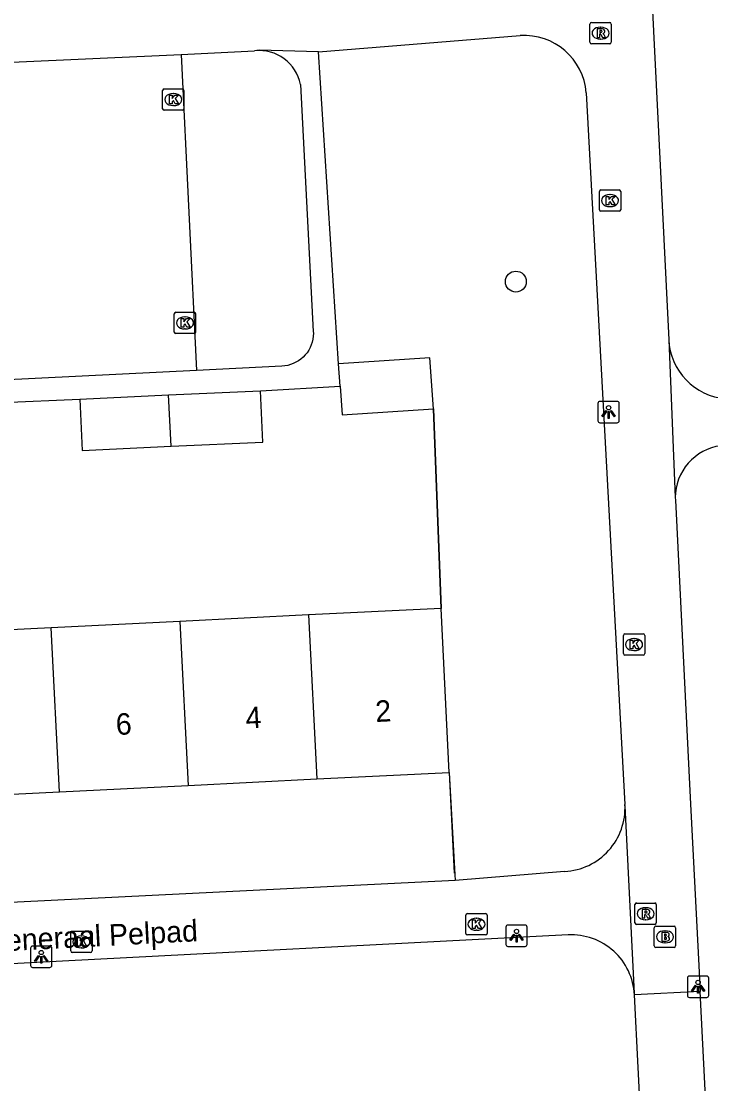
# Model space of a CAD drawing. Extents: x 161084 to 161928, y 385355 to 386522.
# Drawn here: x 161332.38 to 161364.67, y 385622.14 to 385671.84 of the extents above; entities that cross this region are included whole.
import ezdxf

# ---------------------------------------------------------------- set-up
doc = ezdxf.new("R2010")
doc.units = 0
for name, color, linetype in [('IMGEO_Boom', 7, 'Continuous'), ('IMGEO_Brandkraan', 7, 'Continuous'), ('IMGEO_Groenvoorziening', 7, 'Continuous'), ('IMGEO_Hek', 7, 'Continuous'), ('IMGEO_Kolk', 7, 'Continuous'), ('IMGEO_Lichtpunt', 7, 'Continuous'), ('IMGEO_Openbare_ruimte_label', 7, 'Continuous'), ('IMGEO_Pand', 7, 'Continuous'), ('IMGEO_Pand_nummerreeks', 7, 'Continuous'), ('IMGEO_Rijbaan_lokaal_open', 7, 'Continuous'), ('IMGEO_Rioolput', 7, 'Continuous'), ('IMGEO_Voetpad_open', 7, 'Continuous')]:
    doc.layers.add(name, color=color, linetype=linetype)

msp = doc.modelspace()

# ---------------------------------------------------------------- linework, layer by layer
at = {"layer": 'IMGEO_Boom'}
msp.add_circle((161355.54, 385659.662), 0.489, dxfattribs=at)
at = {"layer": 'IMGEO_Brandkraan'}
for p, q in [((161362.02, 385628.59), (161362.02, 385629.442)), ((161362.095, 385629.516), (161362.947, 385629.516)), ((161362.508, 385629.296), (161362.533, 385629.296)), ((161363.021, 385629.442), (161363.021, 385628.59)), ((161362.531, 385628.736), (161362.506, 385628.736)), ((161362.947, 385628.516), (161362.095, 385628.516))]:
    msp.add_line(p, q, dxfattribs=at)
for points in [[(161362.02, 385628.59), (161362.02, 385629.442)], [(161362.095, 385629.516), (161362.947, 385629.516)], [(161362.368, 385629.216), (161362.368, 385628.816), (161362.581, 385628.816)], [(161362.599, 385629.216), (161362.368, 385629.216)], [(161362.547, 385629.135), (161362.493, 385629.135), (161362.493, 385629.059)], [(161363.021, 385629.442), (161363.021, 385628.59)], [(161362.493, 385629.059), (161362.546, 385629.059)], [(161362.555, 385628.983), (161362.493, 385628.983), (161362.493, 385628.902)], [(161362.493, 385628.902), (161362.555, 385628.902)], [(161362.947, 385628.516), (161362.095, 385628.516)]]:
    msp.add_lwpolyline(points, dxfattribs=at)
for centre, radius, start, end in [((161362.097, 385629.44), 0.0765, 91.552, 178.448), ((161362.097, 385629.44), 0.0765, 91.552, 178.448), ((161362.548, 385629.097), 0.0379, 267.8285, 90.9355), ((161362.603, 385629.071), 0.145, 59.4692, 91.5367), ((161362.628, 385629.118), 0.0922, 285.5137, 58.1501), ((161362.945, 385629.44), 0.0765, 1.552, 88.448), ((161362.945, 385629.44), 0.0765, 1.552, 88.448), ((161362.556, 385628.942), 0.0404, 269.8759, 90.5077), ((161362.587, 385629.067), 0.251, 268.6676, 293.5347), ((161362.633, 385628.926), 0.105, 301.3115, 78.989), ((161362.097, 385628.592), 0.0765, 181.552, 268.448), ((161362.097, 385628.592), 0.0765, 181.552, 268.448), ((161362.945, 385628.592), 0.0765, 271.552, 358.448), ((161362.945, 385628.592), 0.0765, 271.552, 358.448)]:
    msp.add_arc(centre, radius, start, end, dxfattribs=at)
for centre, major_axis, ratio, start_param, end_param in [((161362.507, 385629.016), (-0.387, 0.002), 0.722429, 4.712389, 7.853982), ((161362.532, 385629.016), (-0.39, 0.002), 0.717154, 1.570796, 4.712389)]:
    msp.add_ellipse(centre, major_axis=major_axis, ratio=ratio, start_param=start_param, end_param=end_param, dxfattribs=at)
at = {"layer": 'IMGEO_Groenvoorziening'}
for points in [[(161351.677, 385653.717), (161352.039, 385644.38)], [(161352.422, 385636.709), (161352.704, 385631.654)]]:
    msp.add_lwpolyline(points, dxfattribs=at)
at = {"layer": 'IMGEO_Hek'}
for points in [[(161352.039, 385644.38), (161351.677, 385653.717)], [(161352.422, 385636.709), (161352.657, 385631.989)]]:
    msp.add_lwpolyline(points, dxfattribs=at)
at = {"layer": 'IMGEO_Kolk'}
for p, q in [((161339, 385667.752), (161339, 385668.604)), ((161339.075, 385668.678), (161339.927, 385668.678)), ((161339.488, 385668.458), (161339.513, 385668.458)), ((161340.001, 385668.604), (161340.001, 385667.752)), ((161339.511, 385667.898), (161339.486, 385667.898)), ((161339.927, 385667.678), (161339.075, 385667.678)), ((161359.524, 385663.951), (161360.376, 385663.951)), ((161359.449, 385663.025), (161359.449, 385663.877)), ((161359.937, 385663.731), (161359.962, 385663.731)), ((161360.45, 385663.877), (161360.45, 385663.025)), ((161360.376, 385662.951), (161359.524, 385662.951)), ((161359.96, 385663.171), (161359.935, 385663.171)), ((161339.547, 385657.304), (161339.547, 385658.156)), ((161339.622, 385658.23), (161340.474, 385658.23)), ((161340.035, 385658.01), (161340.06, 385658.01)), ((161340.548, 385658.156), (161340.548, 385657.304)), ((161340.058, 385657.45), (161340.033, 385657.45)), ((161340.474, 385657.23), (161339.622, 385657.23)), ((161360.574, 385642.26), (161360.574, 385643.112)), ((161360.649, 385643.186), (161361.501, 385643.186)), ((161361.575, 385643.112), (161361.575, 385642.26)), ((161361.062, 385642.966), (161361.087, 385642.966)), ((161361.501, 385642.186), (161360.649, 385642.186)), ((161361.085, 385642.406), (161361.06, 385642.406)), ((161353.271, 385630.102), (161354.123, 385630.102)), ((161353.196, 385629.176), (161353.196, 385630.028)), ((161353.684, 385629.882), (161353.709, 385629.882)), ((161354.197, 385630.028), (161354.197, 385629.176)), ((161334.698, 385628.352), (161334.698, 385629.204)), ((161334.773, 385629.278), (161335.625, 385629.278)), ((161335.699, 385629.204), (161335.699, 385628.352)), ((161354.123, 385629.102), (161353.271, 385629.102)), ((161353.707, 385629.322), (161353.682, 385629.322)), ((161335.186, 385629.058), (161335.211, 385629.058)), ((161335.625, 385628.278), (161334.773, 385628.278)), ((161335.209, 385628.498), (161335.184, 385628.498))]:
    msp.add_line(p, q, dxfattribs=at)
for points in [[(161339, 385667.752), (161339, 385668.604)], [(161339.075, 385668.678), (161339.927, 385668.678)], [(161339.321, 385668.378), (161339.444, 385668.378), (161339.444, 385668.227), (161339.574, 385668.378), (161339.738, 385668.378), (161339.592, 385668.227), (161339.745, 385667.978), (161339.593, 385667.978), (161339.508, 385668.142), (161339.444, 385668.075), (161339.444, 385667.978), (161339.321, 385667.978), (161339.321, 385668.378)], [(161340.001, 385668.604), (161340.001, 385667.752)], [(161339.927, 385667.678), (161339.075, 385667.678)], [(161359.524, 385663.951), (161360.376, 385663.951)], [(161359.449, 385663.025), (161359.449, 385663.877)], [(161359.77, 385663.651), (161359.893, 385663.651), (161359.893, 385663.5), (161360.023, 385663.651), (161360.187, 385663.651), (161360.041, 385663.5), (161360.194, 385663.251), (161360.042, 385663.251), (161359.957, 385663.415), (161359.893, 385663.348), (161359.893, 385663.251), (161359.77, 385663.251), (161359.77, 385663.651)], [(161360.45, 385663.877), (161360.45, 385663.025)], [(161360.376, 385662.951), (161359.524, 385662.951)], [(161339.547, 385657.304), (161339.547, 385658.156)], [(161339.622, 385658.23), (161340.474, 385658.23)], [(161339.868, 385657.93), (161339.991, 385657.93), (161339.991, 385657.779), (161340.121, 385657.93), (161340.285, 385657.93), (161340.139, 385657.779), (161340.292, 385657.53), (161340.14, 385657.53), (161340.055, 385657.694), (161339.991, 385657.627), (161339.991, 385657.53), (161339.868, 385657.53), (161339.868, 385657.93)], [(161340.548, 385658.156), (161340.548, 385657.304)], [(161340.474, 385657.23), (161339.622, 385657.23)], [(161360.574, 385642.26), (161360.574, 385643.112)], [(161360.649, 385643.186), (161361.501, 385643.186)], [(161361.575, 385643.112), (161361.575, 385642.26)], [(161360.895, 385642.886), (161361.018, 385642.886), (161361.018, 385642.735), (161361.148, 385642.886), (161361.312, 385642.886), (161361.166, 385642.735), (161361.319, 385642.486), (161361.167, 385642.486), (161361.082, 385642.65), (161361.018, 385642.583), (161361.018, 385642.486), (161360.895, 385642.486), (161360.895, 385642.886)], [(161361.501, 385642.186), (161360.649, 385642.186)], [(161353.271, 385630.102), (161354.123, 385630.102)], [(161353.196, 385629.176), (161353.196, 385630.028)], [(161353.517, 385629.802), (161353.64, 385629.802), (161353.64, 385629.651), (161353.77, 385629.802), (161353.934, 385629.802), (161353.788, 385629.651), (161353.941, 385629.402), (161353.789, 385629.402), (161353.704, 385629.566), (161353.64, 385629.499), (161353.64, 385629.402), (161353.517, 385629.402), (161353.517, 385629.802)], [(161354.197, 385630.028), (161354.197, 385629.176)], [(161334.698, 385628.352), (161334.698, 385629.204)], [(161334.773, 385629.278), (161335.625, 385629.278)], [(161335.699, 385629.204), (161335.699, 385628.352)], [(161354.123, 385629.102), (161353.271, 385629.102)], [(161335.019, 385628.978), (161335.142, 385628.978), (161335.142, 385628.827), (161335.272, 385628.978), (161335.436, 385628.978), (161335.29, 385628.827), (161335.443, 385628.578), (161335.291, 385628.578), (161335.206, 385628.742), (161335.142, 385628.675), (161335.142, 385628.578), (161335.019, 385628.578), (161335.019, 385628.978)], [(161335.625, 385628.278), (161334.773, 385628.278)]]:
    msp.add_lwpolyline(points, dxfattribs=at)
for centre, start, end in [((161339.077, 385668.602), 91.552, 178.448), ((161339.077, 385668.602), 91.552, 178.448), ((161339.925, 385668.602), 1.552, 88.448), ((161339.925, 385668.602), 1.552, 88.448), ((161339.077, 385667.754), 181.552, 268.448), ((161339.077, 385667.754), 181.552, 268.448), ((161339.925, 385667.754), 271.552, 358.448), ((161339.925, 385667.754), 271.552, 358.448), ((161359.526, 385663.875), 91.552, 178.448), ((161359.526, 385663.875), 91.552, 178.448), ((161360.374, 385663.875), 1.552, 88.448), ((161360.374, 385663.875), 1.552, 88.448), ((161359.526, 385663.027), 181.552, 268.448), ((161359.526, 385663.027), 181.552, 268.448), ((161360.374, 385663.027), 271.552, 358.448), ((161360.374, 385663.027), 271.552, 358.448), ((161339.624, 385658.154), 91.552, 178.448), ((161339.624, 385658.154), 91.552, 178.448), ((161340.472, 385658.154), 1.552, 88.448), ((161340.472, 385658.154), 1.552, 88.448), ((161339.624, 385657.306), 181.552, 268.448), ((161339.624, 385657.306), 181.552, 268.448), ((161340.472, 385657.306), 271.552, 358.448), ((161340.472, 385657.306), 271.552, 358.448), ((161360.651, 385643.11), 91.552, 178.448), ((161360.651, 385643.11), 91.552, 178.448), ((161361.499, 385643.11), 1.552, 88.448), ((161361.499, 385643.11), 1.552, 88.448), ((161360.651, 385642.262), 181.552, 268.448), ((161360.651, 385642.262), 181.552, 268.448), ((161361.499, 385642.262), 271.552, 358.448), ((161361.499, 385642.262), 271.552, 358.448), ((161353.273, 385630.026), 91.552, 178.448), ((161353.273, 385630.026), 91.552, 178.448), ((161354.121, 385630.026), 1.552, 88.448), ((161354.121, 385630.026), 1.552, 88.448), ((161334.775, 385629.202), 91.552, 178.448), ((161334.775, 385629.202), 91.552, 178.448), ((161335.623, 385629.202), 1.552, 88.448), ((161335.623, 385629.202), 1.552, 88.448), ((161353.273, 385629.178), 181.552, 268.448), ((161353.273, 385629.178), 181.552, 268.448), ((161354.121, 385629.178), 271.552, 358.448), ((161354.121, 385629.178), 271.552, 358.448), ((161334.775, 385628.354), 181.552, 268.448), ((161334.775, 385628.354), 181.552, 268.448), ((161335.623, 385628.354), 271.552, 358.448), ((161335.623, 385628.354), 271.552, 358.448)]:
    msp.add_arc(centre, 0.0765, start, end, dxfattribs=at)
for centre, major_axis, ratio, start_param, end_param in [((161339.487, 385668.178), (-0.387, 0.002), 0.722429, 4.712389, 7.853982), ((161339.512, 385668.178), (-0.39, 0.002), 0.717154, 1.570796, 4.712389), ((161359.936, 385663.451), (-0.387, 0.002), 0.722429, 4.712389, 7.853982), ((161359.961, 385663.451), (-0.39, 0.002), 0.717154, 1.570796, 4.712389), ((161340.034, 385657.73), (-0.387, 0.002), 0.722429, 4.712389, 7.853982), ((161340.059, 385657.73), (-0.39, 0.002), 0.717154, 1.570796, 4.712389), ((161361.061, 385642.686), (-0.387, 0.002), 0.722429, 4.712389, 7.853982), ((161361.086, 385642.686), (-0.39, 0.002), 0.717154, 1.570796, 4.712389), ((161353.683, 385629.602), (-0.387, 0.002), 0.722429, 4.712389, 7.853982), ((161353.708, 385629.602), (-0.39, 0.002), 0.717154, 1.570796, 4.712389), ((161335.185, 385628.778), (-0.387, 0.002), 0.722429, 4.712389, 7.853982), ((161335.21, 385628.778), (-0.39, 0.002), 0.717154, 1.570796, 4.712389)]:
    msp.add_ellipse(centre, major_axis=major_axis, ratio=ratio, start_param=start_param, end_param=end_param, dxfattribs=at)
at = {"layer": 'IMGEO_Lichtpunt'}
for p, q in [((161359.381, 385653.965), (161359.381, 385653.158)), ((161359.381, 385653.965), (161359.381, 385653.158)), ((161360.283, 385654.06), (161359.475, 385654.06)), ((161360.283, 385654.06), (161359.475, 385654.06)), ((161360.377, 385653.158), (161360.377, 385653.965)), ((161360.377, 385653.158), (161360.377, 385653.965)), ((161359.475, 385653.064), (161360.283, 385653.064)), ((161359.475, 385653.064), (161360.283, 385653.064)), ((161355.072, 385629.47), (161355.072, 385628.663)), ((161355.072, 385629.47), (161355.072, 385628.663)), ((161355.974, 385629.565), (161355.166, 385629.565)), ((161355.974, 385629.565), (161355.166, 385629.565)), ((161356.068, 385628.663), (161356.068, 385629.47)), ((161356.068, 385628.663), (161356.068, 385629.47)), ((161332.818, 385628.483), (161332.818, 385627.676)), ((161332.818, 385628.483), (161332.818, 385627.676)), ((161333.72, 385628.578), (161332.912, 385628.578)), ((161333.72, 385628.578), (161332.912, 385628.578)), ((161333.814, 385627.676), (161333.814, 385628.483)), ((161333.814, 385627.676), (161333.814, 385628.483)), ((161355.166, 385628.569), (161355.974, 385628.569)), ((161355.166, 385628.569), (161355.974, 385628.569)), ((161332.912, 385627.582), (161333.72, 385627.582)), ((161332.912, 385627.582), (161333.72, 385627.582)), ((161364.474, 385627.179), (161363.666, 385627.179)), ((161364.474, 385627.179), (161363.666, 385627.179)), ((161363.572, 385627.084), (161363.572, 385626.277)), ((161363.572, 385627.084), (161363.572, 385626.277)), ((161364.568, 385626.277), (161364.568, 385627.084)), ((161364.568, 385626.277), (161364.568, 385627.084)), ((161363.666, 385626.183), (161364.474, 385626.183)), ((161363.666, 385626.183), (161364.474, 385626.183))]:
    msp.add_line(p, q, dxfattribs=at)
for points in [[(161359.755, 385653.629), (161359.794, 385653.601), (161359.606, 385653.339), (161359.568, 385653.366), (161359.755, 385653.629)], [(161359.857, 385653.581), (161359.904, 385653.581), (161359.904, 385653.259), (161359.857, 385653.259), (161359.857, 385653.581)], [(161359.967, 385653.601), (161360.005, 385653.628), (161360.192, 385653.366), (161360.153, 385653.338), (161359.967, 385653.601)], [(161355.446, 385629.134), (161355.485, 385629.106), (161355.297, 385628.844), (161355.259, 385628.871), (161355.446, 385629.134)], [(161355.658, 385629.106), (161355.696, 385629.133), (161355.883, 385628.871), (161355.844, 385628.843), (161355.658, 385629.106)], [(161355.548, 385629.086), (161355.595, 385629.086), (161355.595, 385628.764), (161355.548, 385628.764), (161355.548, 385629.086)], [(161333.192, 385628.147), (161333.231, 385628.119), (161333.043, 385627.857), (161333.005, 385627.884), (161333.192, 385628.147)], [(161333.294, 385628.099), (161333.341, 385628.099), (161333.341, 385627.777), (161333.294, 385627.777), (161333.294, 385628.099)], [(161333.404, 385628.119), (161333.442, 385628.146), (161333.629, 385627.884), (161333.59, 385627.856), (161333.404, 385628.119)], [(161363.946, 385626.748), (161363.985, 385626.72), (161363.797, 385626.458), (161363.759, 385626.485), (161363.946, 385626.748)], [(161364.048, 385626.7), (161364.095, 385626.7), (161364.095, 385626.378), (161364.048, 385626.378), (161364.048, 385626.7)], [(161364.158, 385626.72), (161364.196, 385626.747), (161364.383, 385626.485), (161364.344, 385626.457), (161364.158, 385626.72)]]:
    msp.add_lwpolyline(points, dxfattribs=at)
for centre in [(161359.88, 385653.763), (161355.571, 385629.268), (161333.317, 385628.281), (161364.071, 385626.882)]:
    msp.add_circle(centre, 0.0994, dxfattribs=at)
for centre, start, end in [((161359.475, 385653.965), 90, 180), ((161359.475, 385653.965), 90, 180), ((161360.283, 385653.965), 0, 90), ((161360.283, 385653.965), 0, 90), ((161359.475, 385653.158), 180, 270), ((161359.475, 385653.158), 180, 270), ((161360.283, 385653.158), 270, 0), ((161360.283, 385653.158), 270, 360), ((161355.166, 385629.47), 90, 180), ((161355.166, 385629.47), 90, 180), ((161355.974, 385629.47), 0, 90), ((161355.974, 385629.47), 0, 90), ((161355.166, 385628.663), 180, 270), ((161355.166, 385628.663), 180, 270), ((161355.974, 385628.663), 270, 0), ((161355.974, 385628.663), 270, 360), ((161332.912, 385628.483), 90, 180), ((161332.912, 385628.483), 90, 180), ((161333.72, 385628.483), 0, 90), ((161333.72, 385628.483), 0, 90), ((161332.912, 385627.676), 180, 270), ((161332.912, 385627.676), 180, 270), ((161333.72, 385627.676), 270, 0), ((161333.72, 385627.676), 270, 360), ((161363.666, 385627.084), 90, 180), ((161363.666, 385627.084), 90, 180), ((161364.474, 385627.084), 0, 90), ((161364.474, 385627.084), 0, 90), ((161363.666, 385626.277), 180, 270), ((161363.666, 385626.277), 180, 270), ((161364.474, 385626.277), 270, 0), ((161364.474, 385626.277), 270, 360)]:
    msp.add_arc(centre, 0.0946, start, end, dxfattribs=at)
at = {"layer": 'IMGEO_Pand'}
for points in [[(161351.677, 385653.717), (161351.516, 385656.102), (161347.242, 385655.814)], [(161347.311, 385654.779), (161347.242, 385655.814)], [(161339.284, 385654.359), (161343.583, 385654.556)], [(161339.404, 385651.958), (161343.693, 385652.154), (161343.583, 385654.556)], [(161347.311, 385654.779), (161347.402, 385653.43), (161351.677, 385653.717)], [(161335.129, 385654.169), (161339.284, 385654.359)], [(161335.129, 385654.169), (161335.239, 385651.767), (161339.404, 385651.958)], [(161339.404, 385651.958), (161339.284, 385654.359)], [(161345.838, 385644.071), (161339.813, 385643.77)], [(161352.039, 385644.38), (161345.838, 385644.071)], [(161345.838, 385644.071), (161346.221, 385636.4)], [(161352.422, 385636.709), (161352.039, 385644.38)], [(161339.813, 385643.77), (161333.788, 385643.47)], [(161339.813, 385643.77), (161340.196, 385636.099)], [(161333.788, 385643.47), (161327.762, 385643.169)], [(161334.171, 385635.799), (161333.788, 385643.47)], [(161346.221, 385636.4), (161352.422, 385636.709)], [(161334.171, 385635.799), (161340.196, 385636.099)], [(161340.196, 385636.099), (161346.221, 385636.4)], [(161328.145, 385635.498), (161334.171, 385635.799)]]:
    msp.add_lwpolyline(points, dxfattribs=at)
at = {"layer": 'IMGEO_Rijbaan_lokaal_open'}
for points in [[(161331.944, 385669.924), (161339.868, 385670.281)], [(161339.868, 385670.281), (161340.58, 385655.511)], [(161340.58, 385655.511), (161331.457, 385655.048), (161319.602, 385654.445)]]:
    msp.add_lwpolyline(points, dxfattribs=at)
at = {"layer": 'IMGEO_Rioolput'}
for p, q in [((161359.005, 385670.858), (161359.005, 385671.71)), ((161359.08, 385671.784), (161359.932, 385671.784)), ((161359.493, 385671.564), (161359.518, 385671.564)), ((161360.006, 385671.71), (161360.006, 385670.858)), ((161359.516, 385671.004), (161359.491, 385671.004)), ((161359.932, 385670.784), (161359.08, 385670.784)), ((161361.19, 385630.597), (161362.042, 385630.597)), ((161361.115, 385629.671), (161361.115, 385630.523)), ((161361.603, 385630.377), (161361.628, 385630.377)), ((161362.116, 385630.523), (161362.116, 385629.671)), ((161362.042, 385629.597), (161361.19, 385629.597)), ((161361.626, 385629.817), (161361.601, 385629.817))]:
    msp.add_line(p, q, dxfattribs=at)
for points in [[(161359.005, 385670.858), (161359.005, 385671.71)], [(161359.08, 385671.784), (161359.932, 385671.784)], [(161359.594, 385671.482), (161359.342, 385671.484), (161359.342, 385671.084)], [(161359.52, 385671.403), (161359.466, 385671.403), (161359.466, 385671.322)], [(161360.006, 385671.71), (161360.006, 385670.858)], [(161359.342, 385671.084), (161359.466, 385671.084), (161359.466, 385671.246), (161359.477, 385671.246)], [(161359.466, 385671.322), (161359.518, 385671.322)], [(161359.524, 385671.217), (161359.595, 385671.084), (161359.735, 385671.084), (161359.67, 385671.21)], [(161359.932, 385670.784), (161359.08, 385670.784)], [(161361.19, 385630.597), (161362.042, 385630.597)], [(161361.115, 385629.671), (161361.115, 385630.523)], [(161361.704, 385630.295), (161361.452, 385630.297), (161361.452, 385629.897)], [(161361.63, 385630.216), (161361.576, 385630.216), (161361.576, 385630.135)], [(161361.576, 385630.135), (161361.628, 385630.135)], [(161362.116, 385630.523), (161362.116, 385629.671)], [(161362.042, 385629.597), (161361.19, 385629.597)], [(161361.452, 385629.897), (161361.576, 385629.897), (161361.576, 385630.059), (161361.587, 385630.059)], [(161361.634, 385630.03), (161361.705, 385629.897), (161361.845, 385629.897), (161361.78, 385630.023)]]:
    msp.add_lwpolyline(points, dxfattribs=at)
for centre, radius, start, end in [((161359.082, 385671.708), 0.0765, 91.552, 178.448), ((161359.082, 385671.708), 0.0765, 91.552, 178.448), ((161359.526, 385671.307), 0.0964, 77.0061, 93.1865), ((161359.54, 385671.364), 0.0378, 276.6634, 79.6772), ((161359.593, 385671.372), 0.109, 350.3612, 89.416), ((161359.591, 385671.372), 0.112, 277.5842, 350.9817), ((161359.93, 385671.708), 0.0765, 1.552, 88.448), ((161359.93, 385671.708), 0.0765, 1.552, 88.448), ((161359.082, 385670.86), 0.0765, 181.552, 268.448), ((161359.082, 385670.86), 0.0765, 181.552, 268.448), ((161359.476, 385671.193), 0.0533, 26.0293, 88.6989), ((161359.502, 385671.511), 0.19, 274.7715, 282.9687), ((161359.575, 385671.157), 0.108, 29.5134, 73.7905), ((161359.93, 385670.86), 0.0765, 271.552, 358.448), ((161359.93, 385670.86), 0.0765, 271.552, 358.448), ((161361.192, 385630.521), 0.0765, 91.552, 178.448), ((161361.192, 385630.521), 0.0765, 91.552, 178.448), ((161362.04, 385630.521), 0.0765, 1.552, 88.448), ((161362.04, 385630.521), 0.0765, 1.552, 88.448), ((161361.612, 385630.324), 0.19, 274.7715, 282.9687), ((161361.636, 385630.12), 0.0964, 77.0061, 93.1865), ((161361.65, 385630.177), 0.0378, 276.6634, 79.6772), ((161361.703, 385630.185), 0.109, 350.3612, 89.416), ((161361.701, 385630.185), 0.112, 277.5842, 350.9817), ((161361.192, 385629.673), 0.0765, 181.552, 268.448), ((161361.192, 385629.673), 0.0765, 181.552, 268.448), ((161361.586, 385630.006), 0.0533, 26.0293, 88.6989), ((161361.685, 385629.97), 0.108, 29.5134, 73.7905), ((161362.04, 385629.673), 0.0765, 271.552, 358.448), ((161362.04, 385629.673), 0.0765, 271.552, 358.448)]:
    msp.add_arc(centre, radius, start, end, dxfattribs=at)
for centre, major_axis, ratio, start_param, end_param in [((161359.492, 385671.284), (-0.387, 0.002), 0.722429, 4.712389, 7.853982), ((161359.517, 385671.284), (-0.39, 0.002), 0.717154, 1.570796, 4.712389), ((161361.602, 385630.097), (-0.387, 0.002), 0.722429, 4.712389, 7.853982), ((161361.627, 385630.097), (-0.39, 0.002), 0.717154, 1.570796, 4.712389)]:
    msp.add_ellipse(centre, major_axis=major_axis, ratio=ratio, start_param=start_param, end_param=end_param, dxfattribs=at)
at = {"layer": 'IMGEO_Voetpad_open'}
for points in [[(161358.884, 385733.846), (161362.696, 385656.941)], [(161346.292, 385670.411), (161355.738, 385671.168)], [(161339.868, 385670.281), (161343.309, 385670.461)], [(161346.292, 385670.411), (161343.518, 385670.489), (161343.309, 385670.461)], [(161347.242, 385655.814), (161346.292, 385670.411)], [(161345.461, 385668.879), (161346.057, 385657.333), (161346.059, 385657.246), (161346.053, 385657.107), (161346.034, 385656.97), (161346.002, 385656.835), (161345.959, 385656.704), (161345.905, 385656.576), (161345.839, 385656.455), (161345.762, 385656.339), (161345.676, 385656.231), (161345.58, 385656.131), (161345.476, 385656.04), (161345.364, 385655.959), (161345.245, 385655.887), (161345.12, 385655.827), (161344.991, 385655.779), (161344.857, 385655.742), (161344.721, 385655.717), (161344.583, 385655.704), (161340.58, 385655.511)], [(161358.834, 385668.49), (161360.647, 385635.203)], [(161362.696, 385656.941), (161362.721, 385656.681), (161362.769, 385656.425), (161362.839, 385656.174), (161362.932, 385655.93), (161363.046, 385655.696), (161363.181, 385655.473), (161363.335, 385655.262), (161363.507, 385655.067), (161363.696, 385654.887), (161363.9, 385654.725), (161364.118, 385654.582), (161364.348, 385654.459), (161364.588, 385654.357), (161364.836, 385654.277), (161365.091, 385654.219), (161365.349, 385654.184), (161365.609, 385654.173), (161365.749, 385654.176), (161379.269, 385654.847), (161388.176, 385655.289)], [(161362.696, 385656.941), (161363.004, 385649.56)], [(161343.583, 385654.556), (161347.311, 385654.779)], [(161331.481, 385654.008), (161335.129, 385654.169)], [(161378.25, 385636.489), (161378.195, 385637.577), (161380.118, 385637.669), (161379.391, 385652.666), (161365.343, 385652.004), (161365.124, 385651.984), (161364.909, 385651.944), (161364.697, 385651.886), (161364.492, 385651.808), (161364.294, 385651.713), (161364.106, 385651.6), (161363.928, 385651.471), (161363.763, 385651.327), (161363.611, 385651.168), (161363.474, 385650.997), (161363.353, 385650.814), (161363.249, 385650.621), (161363.162, 385650.419), (161363.094, 385650.211), (161363.045, 385649.997), (161363.015, 385649.779), (161363.004, 385649.56)], [(161363.004, 385649.56), (161363.007, 385649.433), (161363.707, 385635.535), (161364.165, 385626.458)], [(161361.09, 385626.303), (161361.092, 385626.358), (161360.656, 385635.14), (161360.647, 385635.203)], [(161352.704, 385631.654), (161310.128, 385629.541)], [(161357.823, 385632.072), (161352.704, 385631.654)], [(161357.99, 385629.103), (161307.623, 385626.483)], [(161364.165, 385626.458), (161361.09, 385626.303)], [(161363.866, 385570.302), (161363.733, 385574.245), (161361.948, 385609.312), (161361.09, 385626.303)], [(161364.763, 385614.768), (161364.165, 385626.458)]]:
    msp.add_lwpolyline(points, dxfattribs=at)
for centre, radius, start, end in [((161355.944, 385668.278), 2.897, 4.1962, 94.085), ((161343.516, 385668.488), 1.984, 11.3755, 95.9831), ((161357.672, 385635.048), 2.979, 272.9127, 2.9897), ((161358.143, 385626.157), 2.95, 2.8426, 92.9791)]:
    msp.add_arc(centre, radius, start, end, dxfattribs=at)

# ---------------------------------------------------------------- texts
at = {"layer": 'IMGEO_Openbare_ruimte_label'}
msp.add_text('Generaal Pelpad', height=1, rotation=2.9797, dxfattribs=at).set_placement((161330.65, 385628.291))
at = {"layer": 'IMGEO_Pand_nummerreeks'}
for s, p in [('2', (161348.982, 385639.06)), ('4', (161342.908, 385638.757)), ('6', (161336.833, 385638.454))]:
    msp.add_text(s, height=1, rotation=2.8551, dxfattribs=at).set_placement(p)

doc.saveas('drawing.dxf')
